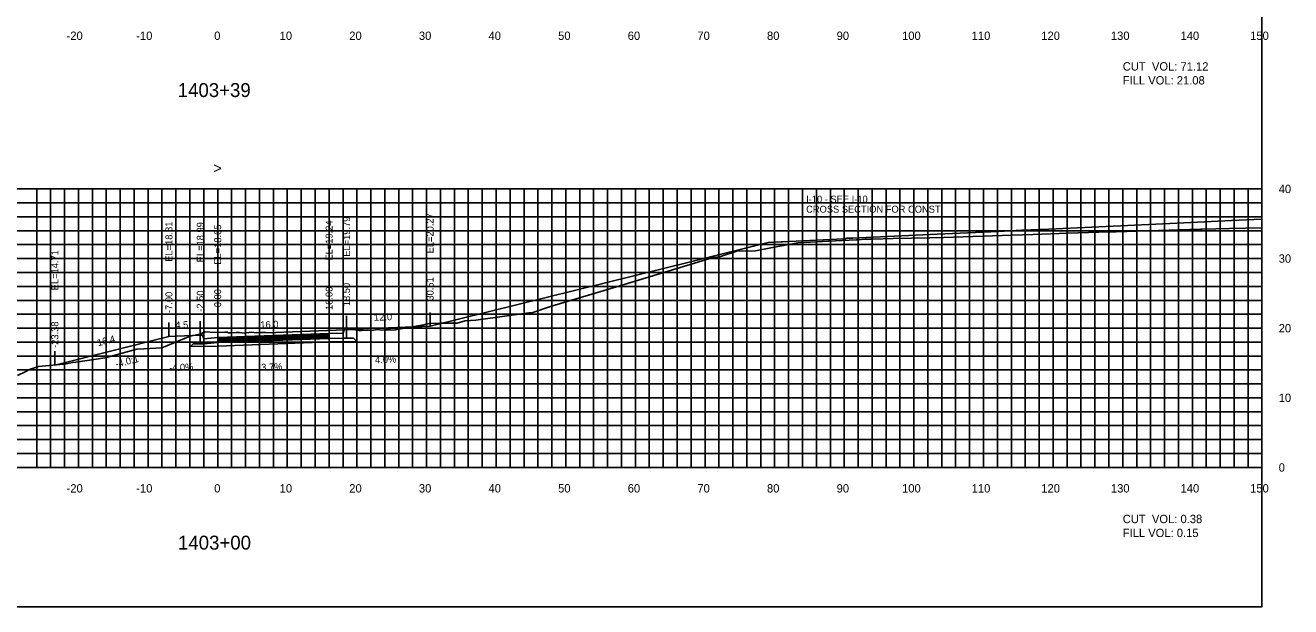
# Model space of a CAD drawing. Extents: x 1797652 to 1804159, y 242516 to 246906.
# Drawn here: x 1802956.9 to 1803138.6, y 242516 to 242599.5 of the extents above; entities that cross this region are included whole.
import ezdxf

# ---------------------------------------------------------------- set-up
doc = ezdxf.new("R2010")
doc.units = 0
for name, color, linetype in [('1', 7, 'Continuous'), ('10', 7, 'Continuous'), ('2', 7, 'Continuous'), ('3', 7, 'Continuous'), ('31', 7, 'Continuous'), ('4', 7, 'Continuous'), ('60', 7, 'Continuous'), ('BASE', 7, 'Continuous'), ('CL-CNST', 7, 'Continuous'), ('Level 62', 7, 'Continuous'), ('LOWER BINDER', 7, 'Continuous'), ('M-ROADS', 7, 'Continuous'), ('UPPER BINDER', 7, 'Continuous')]:
    doc.layers.add(name, color=color, linetype=linetype)

msp = doc.modelspace()

# ---------------------------------------------------------------- linework, layer by layer
for p, q in [((1802977.49, 242554.81), (1802977.49, 242556.81)), ((1802981.99, 242554.99), (1802981.99, 242556.99)), ((1803000.49, 242555.24), (1803000.49, 242557.24)), ((1803002.99, 242555.79), (1803002.99, 242557.79)), ((1803015, 242556.27), (1803015, 242558.27)), ((1802984.49, 242554.65), (1802984.49, 242556.65)), ((1802961.11, 242550.71), (1802961.11, 242552.71))]:
    msp.add_line(p, q)
for points in [[(1802834.49, 242516), (1803134.49, 242516), (1803134.49, 242706), (1802834.49, 242706)], [(1802984.49, 242554.65), (1802982.49, 242554.49), (1802982.32, 242554.99), (1802981.99, 242554.99), (1802981.98, 242553.77), (1802982.48, 242553.77), (1802984.49, 242553.93)], [(1803000.49, 242555.24), (1803002.49, 242555.29), (1803002.66, 242555.79), (1803002.99, 242555.79), (1803002.99, 242554.57), (1803002.49, 242554.57), (1803000.49, 242554.52)]]:
    msp.add_lwpolyline(points, close=True)
at = {"layer": '2'}
msp.add_lwpolyline([(1803000.49, 242555.09), (1803000.49, 242555.24), (1802984.49, 242554.65), (1802984.49, 242554.5)], close=True, dxfattribs=at)
at = {"layer": '60'}
for p, q in [((1803134.49, 242536), (1803134.49, 242576)), ((1803134.55, 242576), (1803134.49, 242576)), ((1803134.55, 242566), (1803134.49, 242566)), ((1803134.55, 242556), (1803134.49, 242556)), ((1803134.55, 242546), (1803134.49, 242546)), ((1802834.49, 242536), (1803134.49, 242536)), ((1802964.49, 242535.94), (1802964.49, 242536)), ((1802974.49, 242535.94), (1802974.49, 242536)), ((1802984.49, 242535.94), (1802984.49, 242536)), ((1802994.49, 242535.94), (1802994.49, 242536)), ((1803004.49, 242535.94), (1803004.49, 242536)), ((1803014.49, 242535.94), (1803014.49, 242536)), ((1803024.49, 242535.94), (1803024.49, 242536)), ((1803034.49, 242535.94), (1803034.49, 242536)), ((1803044.49, 242535.94), (1803044.49, 242536)), ((1803054.49, 242535.94), (1803054.49, 242536)), ((1803064.49, 242535.94), (1803064.49, 242536)), ((1803074.49, 242535.94), (1803074.49, 242536)), ((1803084.49, 242535.94), (1803084.49, 242536)), ((1803094.49, 242535.94), (1803094.49, 242536)), ((1803104.49, 242535.94), (1803104.49, 242536)), ((1803114.49, 242535.94), (1803114.49, 242536)), ((1803124.49, 242535.94), (1803124.49, 242536)), ((1803134.49, 242535.94), (1803134.49, 242536)), ((1803134.55, 242536), (1803134.49, 242536))]:
    msp.add_line(p, q, dxfattribs=at)
at = {"layer": 'BASE'}
msp.add_lwpolyline([(1802984.49, 242553.93), (1803000.49, 242554.52), (1803002.49, 242554.57), (1803002.99, 242554.57), (1803003.99, 242554.59), (1803004.47, 242554.11), (1803000.49, 242554.02), (1802984.49, 242553.43), (1802980.58, 242553.35), (1802980.98, 242553.75), (1802981.98, 242553.77), (1802982.48, 242553.77)], close=True, dxfattribs=at)
at = {"layer": 'CL-CNST'}
for points in [[(1803015, 242556.27), (1803052.59, 242565.59), (1803063.57, 242568.31), (1803065.43, 242568.4), (1803065.6, 242568.41), (1803073.44, 242568.77), (1803074.62, 242568.82), (1803074.69, 242568.89), (1803074.7, 242568.9), (1803074.84, 242568.91), (1803075.71, 242568.94), (1803077.62, 242569.03), (1803087.85, 242569.5), (1803096.64, 242569.91), (1803099.99, 242570.06), (1803103.87, 242570.24), (1803112.13, 242570.62), (1803119.23, 242570.95), (1803124.27, 242571.18), (1803130.09, 242571.45), (1803134.49, 242571.65)], [(1802961.11, 242550.71), (1802977.49, 242554.81), (1802981.99, 242554.99), (1802982.32, 242554.99), (1802982.49, 242554.49), (1802984.49, 242554.65), (1803000.49, 242555.24), (1803002.49, 242555.29), (1803002.66, 242555.79), (1803002.99, 242555.79), (1803015, 242556.27)]]:
    msp.add_lwpolyline(points, dxfattribs=at)
at = {"layer": 'Level 62'}
for p, q in [((1802834.49, 242576), (1803134.49, 242576)), ((1802958.49, 242536), (1802958.49, 242576)), ((1802960.49, 242536), (1802960.49, 242576)), ((1802962.49, 242536), (1802962.49, 242576)), ((1802964.49, 242536), (1802964.49, 242576)), ((1802966.49, 242536), (1802966.49, 242576)), ((1802968.49, 242536), (1802968.49, 242576)), ((1802970.49, 242536), (1802970.49, 242576)), ((1802972.49, 242536), (1802972.49, 242576)), ((1802974.49, 242536), (1802974.49, 242576)), ((1802976.49, 242536), (1802976.49, 242576)), ((1802978.49, 242536), (1802978.49, 242576)), ((1802980.49, 242536), (1802980.49, 242576)), ((1802982.49, 242536), (1802982.49, 242576)), ((1802984.49, 242536), (1802984.49, 242576)), ((1802986.49, 242536), (1802986.49, 242576)), ((1802988.49, 242536), (1802988.49, 242576)), ((1802990.49, 242536), (1802990.49, 242576)), ((1802992.49, 242536), (1802992.49, 242576)), ((1802994.49, 242536), (1802994.49, 242576)), ((1802996.49, 242536), (1802996.49, 242576)), ((1802998.49, 242536), (1802998.49, 242576)), ((1803000.49, 242536), (1803000.49, 242576)), ((1803002.49, 242536), (1803002.49, 242576)), ((1803004.49, 242536), (1803004.49, 242576)), ((1803006.49, 242536), (1803006.49, 242576)), ((1803008.49, 242536), (1803008.49, 242576)), ((1803010.49, 242536), (1803010.49, 242576)), ((1803012.49, 242536), (1803012.49, 242576)), ((1803014.49, 242536), (1803014.49, 242576)), ((1803016.49, 242536), (1803016.49, 242576)), ((1803018.49, 242536), (1803018.49, 242576)), ((1803020.49, 242536), (1803020.49, 242576)), ((1803022.49, 242536), (1803022.49, 242576)), ((1803024.49, 242536), (1803024.49, 242576)), ((1803026.49, 242536), (1803026.49, 242576)), ((1803028.49, 242536), (1803028.49, 242576)), ((1803030.49, 242536), (1803030.49, 242576)), ((1803032.49, 242536), (1803032.49, 242576)), ((1803034.49, 242536), (1803034.49, 242576)), ((1803036.49, 242536), (1803036.49, 242576)), ((1803038.49, 242536), (1803038.49, 242576)), ((1803040.49, 242536), (1803040.49, 242576)), ((1803042.49, 242536), (1803042.49, 242576)), ((1803044.49, 242536), (1803044.49, 242576)), ((1803046.49, 242536), (1803046.49, 242576)), ((1803048.49, 242536), (1803048.49, 242576)), ((1803050.49, 242536), (1803050.49, 242576)), ((1803052.49, 242536), (1803052.49, 242576)), ((1803054.49, 242536), (1803054.49, 242576)), ((1803056.49, 242536), (1803056.49, 242576)), ((1803058.49, 242536), (1803058.49, 242576)), ((1803060.49, 242536), (1803060.49, 242576)), ((1803062.49, 242536), (1803062.49, 242576)), ((1803064.49, 242536), (1803064.49, 242576)), ((1803066.49, 242536), (1803066.49, 242576)), ((1803068.49, 242536), (1803068.49, 242576)), ((1803070.49, 242536), (1803070.49, 242576)), ((1803072.49, 242536), (1803072.49, 242576)), ((1803074.49, 242536), (1803074.49, 242576)), ((1803076.49, 242536), (1803076.49, 242576)), ((1803078.49, 242536), (1803078.49, 242576)), ((1803080.49, 242536), (1803080.49, 242576)), ((1803082.49, 242536), (1803082.49, 242576)), ((1803084.49, 242536), (1803084.49, 242576)), ((1803086.49, 242536), (1803086.49, 242576)), ((1803088.49, 242536), (1803088.49, 242576)), ((1803090.49, 242536), (1803090.49, 242576)), ((1803092.49, 242536), (1803092.49, 242576)), ((1803094.49, 242536), (1803094.49, 242576)), ((1803096.49, 242536), (1803096.49, 242576)), ((1803098.49, 242536), (1803098.49, 242576)), ((1803100.49, 242536), (1803100.49, 242576)), ((1803102.49, 242536), (1803102.49, 242576)), ((1803104.49, 242536), (1803104.49, 242576)), ((1803106.49, 242536), (1803106.49, 242576)), ((1803108.49, 242536), (1803108.49, 242576)), ((1803110.49, 242536), (1803110.49, 242576)), ((1803112.49, 242536), (1803112.49, 242576)), ((1803114.49, 242536), (1803114.49, 242576)), ((1803116.49, 242536), (1803116.49, 242576)), ((1803118.49, 242536), (1803118.49, 242576)), ((1803120.49, 242536), (1803120.49, 242576)), ((1803122.49, 242536), (1803122.49, 242576)), ((1803124.49, 242536), (1803124.49, 242576)), ((1803126.49, 242536), (1803126.49, 242576)), ((1803128.49, 242536), (1803128.49, 242576)), ((1803130.49, 242536), (1803130.49, 242576)), ((1803132.49, 242536), (1803132.49, 242576)), ((1803134.49, 242536), (1803134.49, 242576)), ((1802834.49, 242574), (1803134.49, 242574)), ((1802834.49, 242572), (1803134.49, 242572)), ((1802834.49, 242570), (1803134.49, 242570)), ((1802834.49, 242568), (1803134.49, 242568)), ((1802834.49, 242566), (1803134.49, 242566)), ((1802834.49, 242564), (1803134.49, 242564)), ((1802834.49, 242562), (1803134.49, 242562)), ((1802834.49, 242560), (1803134.49, 242560)), ((1802834.49, 242558), (1803134.49, 242558)), ((1802834.49, 242556), (1803134.49, 242556)), ((1802834.49, 242554), (1803134.49, 242554)), ((1802834.49, 242552), (1803134.49, 242552)), ((1802834.49, 242550), (1803134.49, 242550)), ((1802834.49, 242548), (1803134.49, 242548)), ((1802834.49, 242546), (1803134.49, 242546)), ((1802834.49, 242544), (1803134.49, 242544)), ((1802834.49, 242542), (1803134.49, 242542)), ((1802834.49, 242540), (1803134.49, 242540)), ((1802834.49, 242538), (1803134.49, 242538)), ((1802834.49, 242536), (1803134.49, 242536))]:
    msp.add_line(p, q, dxfattribs=at)
at = {"layer": 'LOWER BINDER'}
for points in [[(1802984.49, 242554.12), (1802984.49, 242554.31), (1803000.49, 242554.9), (1803000.49, 242554.71)], [(1802984.49, 242553.93), (1802984.49, 242554.12), (1803000.49, 242554.71), (1803000.49, 242554.52)]]:
    msp.add_lwpolyline(points, close=True, dxfattribs=at)
at = {"layer": 'M-ROADS'}
msp.add_lwpolyline([(1802955.76, 242549.21), (1802956.92, 242549.77), (1802957.45, 242550.05), (1802958.74, 242550.52), (1802962.34, 242550.81), (1802962.72, 242550.9), (1802963.63, 242551.06), (1802964.11, 242551.13), (1802968.34, 242551.75), (1802972.89, 242552.99), (1802973.88, 242553.04), (1802976.48, 242553.16), (1802980.54, 242554.86), (1802981.91, 242555.16), (1802982.69, 242555.47), (1802984.1, 242555.39), (1802985.53, 242555.41), (1802985.93, 242555.41), (1802985.98, 242555.35), (1802986.48, 242555.34), (1802987.15, 242555.37), (1802987.64, 242555.37), (1802988.31, 242555.28), (1802988.58, 242555.31), (1802989.37, 242555.42), (1802990.08, 242555.35), (1802990.46, 242555.38), (1802991.4, 242555.38), (1802991.68, 242555.34), (1802993.98, 242555.43), (1803004.02, 242555.79), (1803004.82, 242555.67), (1803005.19, 242555.68), (1803005.99, 242555.72), (1803006.38, 242555.67), (1803006.55, 242555.69), (1803007.47, 242555.8), (1803008.01, 242555.73), (1803008.55, 242555.76), (1803009.33, 242555.78), (1803009.75, 242555.73), (1803014.07, 242556.5), (1803014.68, 242556.62), (1803014.88, 242556.65), (1803016.38, 242556.74), (1803018.22, 242556.74), (1803018.91, 242556.74), (1803020.05, 242557.04), (1803021.57, 242557.17), (1803029.17, 242558.22), (1803029.61, 242558.22), (1803032.44, 242559.15), (1803042.25, 242562.08), (1803055.65, 242566.17), (1803056.59, 242566.26), (1803059.04, 242567.08), (1803061.75, 242567.11), (1803063.68, 242567.47), (1803064.72, 242567.67), (1803067.83, 242568.25), (1803072.21, 242568.49), (1803076.22, 242568.69), (1803076.48, 242568.71), (1803077.48, 242568.77), (1803078.61, 242568.8), (1803081.51, 242568.86), (1803086.76, 242568.98), (1803088.79, 242569.03), (1803098.54, 242569.37), (1803101.64, 242569.47), (1803106.58, 242569.63), (1803112.55, 242569.82), (1803113.09, 242569.84), (1803113.54, 242569.85), (1803125.65, 242570.21), (1803125.9, 242570.22), (1803125.91, 242570.22), (1803129.83, 242570.31), (1803134.49, 242570.41)], dxfattribs=at)
at = {"layer": 'UPPER BINDER'}
msp.add_lwpolyline([(1803000.49, 242554.9), (1803000.49, 242555.09), (1802984.49, 242554.5), (1802984.49, 242554.31)], close=True, dxfattribs=at)

# ---------------------------------------------------------------- texts
msp.add_text('-4.0:1', height=1, rotation=14.0362).set_placement((1802969.91, 242550.34))
at = {"layer": '1'}
for s, p in [('1403+39', (1802978.75, 242589.2)), ('1403+00', (1802978.79, 242524.2))]:
    msp.add_text(s, height=2, dxfattribs=at).set_placement(p)
at = {"layer": '10'}
for s, p in [('-20', (1802962.79, 242597.4)), ('-10', (1802972.79, 242597.4)), ('0', (1802983.99, 242597.4)), ('10', (1802993.39, 242597.4)), ('20', (1803003.39, 242597.4)), ('30', (1803013.39, 242597.4)), ('40', (1803023.39, 242597.4)), ('50', (1803033.39, 242597.4)), ('60', (1803043.39, 242597.4)), ('70', (1803053.39, 242597.4)), ('80', (1803063.39, 242597.4)), ('90', (1803073.39, 242597.4)), ('100', (1803082.79, 242597.4)), ('110', (1803092.79, 242597.4)), ('120', (1803102.79, 242597.4)), ('130', (1803112.79, 242597.4)), ('140', (1803122.79, 242597.4)), ('150', (1803132.79, 242597.4)), ('CUT  VOL: 71.12', (1803114.49, 242593)), ('FILL VOL: 21.08', (1803114.49, 242591)), ('-20', (1802962.79, 242532.4)), ('-10', (1802972.79, 242532.4)), ('0', (1802983.99, 242532.4)), ('10', (1802993.39, 242532.4)), ('20', (1803003.39, 242532.4)), ('30', (1803013.39, 242532.4)), ('40', (1803023.39, 242532.4)), ('50', (1803033.39, 242532.4)), ('60', (1803043.39, 242532.4)), ('70', (1803053.39, 242532.4)), ('80', (1803063.39, 242532.4)), ('90', (1803073.39, 242532.4)), ('100', (1803082.79, 242532.4)), ('110', (1803092.79, 242532.4)), ('120', (1803102.79, 242532.4)), ('130', (1803112.79, 242532.4)), ('140', (1803122.79, 242532.4)), ('150', (1803132.79, 242532.4)), ('CUT  VOL: 0.38', (1803114.49, 242528)), ('FILL VOL: 0.15', (1803114.49, 242526))]:
    msp.add_text(s, height=1.2, dxfattribs=at).set_placement(p)
at = {"layer": '3'}
for s, p in [('I-10 - SEE I-10', (1803069.01, 242574.03)), ('CROSS SECTION FOR CONST ', (1803069.01, 242572.59))]:
    msp.add_text(s, height=1, dxfattribs=at).set_placement(p)
for s, p in [('EL=19.24', (1803000.99, 242565.71)), ('EL=19.79', (1803003.49, 242566.26)), ('EL=20.27', (1803015.5, 242566.74)), ('EL=18.81', (1802977.99, 242565.54)), ('EL=18.99', (1802982.49, 242565.46)), ('EL=18.65', (1802984.99, 242565.12)), ('EL=14.71', (1802961.61, 242561.44)), ('18.50', (1803003.49, 242559.16)), ('30.51', (1803015.5, 242559.97)), ('-7.00', (1802977.99, 242558.18)), ('-2.50', (1802982.49, 242558.36)), ('0.00', (1802984.99, 242559.01)), ('16.00', (1803000.99, 242558.61)), ('-23.38', (1802961.61, 242553.17))]:
    msp.add_text(s, height=1, rotation=90, dxfattribs=at).set_placement(p)
at = {"layer": '31'}
for s, p in [('40', (1803136.89, 242575.4)), ('30', (1803136.89, 242565.4)), ('20', (1803136.89, 242555.4)), ('10', (1803136.89, 242545.4)), ('0', (1803136.89, 242535.4))]:
    msp.add_text(s, height=1.2, dxfattribs=at).set_placement(p)
at = {"layer": '4'}
for s, rotation, p in [('4.5', 2.2906, (1802978.42, 242555.95)), ('16.0', 2.1125, (1802990.63, 242555.98)), ('12.0', 2.2906, (1803006.96, 242557.05)), ('16.4', 14.0362, (1802967.31, 242553.4)), ('4.0%', 2.2906, (1803007.11, 242550.95)), ('-4.0%', 2.2906, (1802977.53, 242549.81)), ('3.7%', 2.1125, (1802990.76, 242549.88))]:
    msp.add_text(s, height=1, rotation=rotation, dxfattribs=at).set_placement(p)
at = {"layer": '60'}
msp.add_text('>', height=1.5, dxfattribs=at).set_placement((1802983.88, 242578.25))

doc.saveas('drawing.dxf')
